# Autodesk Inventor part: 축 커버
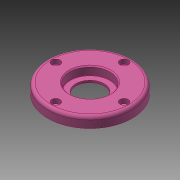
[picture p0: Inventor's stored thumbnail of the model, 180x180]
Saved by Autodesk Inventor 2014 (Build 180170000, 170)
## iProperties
Created: 2015-10
Part Number: 축 커버
Document SubType Name: Modeling
Designer: mdu
Density: 1 g/cm^3
Material: 강철, 연강
Appearance: 분홍색
d0: 10.000 mm
d1: 0.00 deg
d2: 3.000 mm
d3: 0.00 deg
d6: 27.000 mm
d8: 38.000 mm
d9: 8.000 mm
d13: 40.000 mm
d14: 3.000 mm
d15: 0.00 deg
d16: 4.500 mm
d18: 8.000 mm
d19: 4.400 mm
d23: 4.000 ul
d24: 360.00 deg
d26: 3.000 mm
d27: 0.300 mm
d28: 1.000 mm
Author: mdu
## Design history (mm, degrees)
sketch "스케치1"
  geometry: C1 r 40 at (0, 0) reference; C2 r 26 at (0, 0) reference; 1 further point
  node "참조1"
  node "참조2"
extrude "돌출1" new body sketch "스케치1" distance "d0" = 10; taper "d1" = 0 deg
extrude "돌출2" join sketch "스케치1" distance "d2" = 3; taper "d3" = 0 deg
hole "구멍1" diameter "d6" = 27; stored, may be unused: countersink angle "d10" = 90 deg, drill point angle "d12" = 118 deg; dims "d4" = 10, "d5" = 10, "d7" = 6, "d8" = 38, "d9" = 8, "d11" = 8
sketch "스케치2"
  geometry: C1 r 20 at (0, 0); 1 further point
  constraints: 1 centre point, 1 coincident
  dimensions: "d13" = 40 diameter of C1
extrude "돌출3" cut sketch "스케치2" distance "d14" = 3; taper "d15" = 0 deg
sketch "스케치3"
  geometry: C1 r 1.621 at (0, 32.5) reference; 1 further point
hole "구멍2" sketch "스케치3" at (0, 32.5) diameter "d16" = 4.5; stored, may be unused: countersink angle "d20" = 90 deg, drill point angle "d22" = 118 deg; dims "d17" = 6, "d18" = 8, "d19" = 4.4, "d21" = 8
fillet "모깎기1" dims "d26" = 3, "d27" = 0.3
chamfer "모따기1" distance "d28" = 1; stored, may be unused: second distance "d29" = 2, angle "d30" = 45 deg
node "솔리드1"
pattern_circular "원형 패턴1" dims count "d23" = 4, angle "d24" = 360 deg
node "참조3"
